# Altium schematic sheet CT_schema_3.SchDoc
size 334 x 183 mm
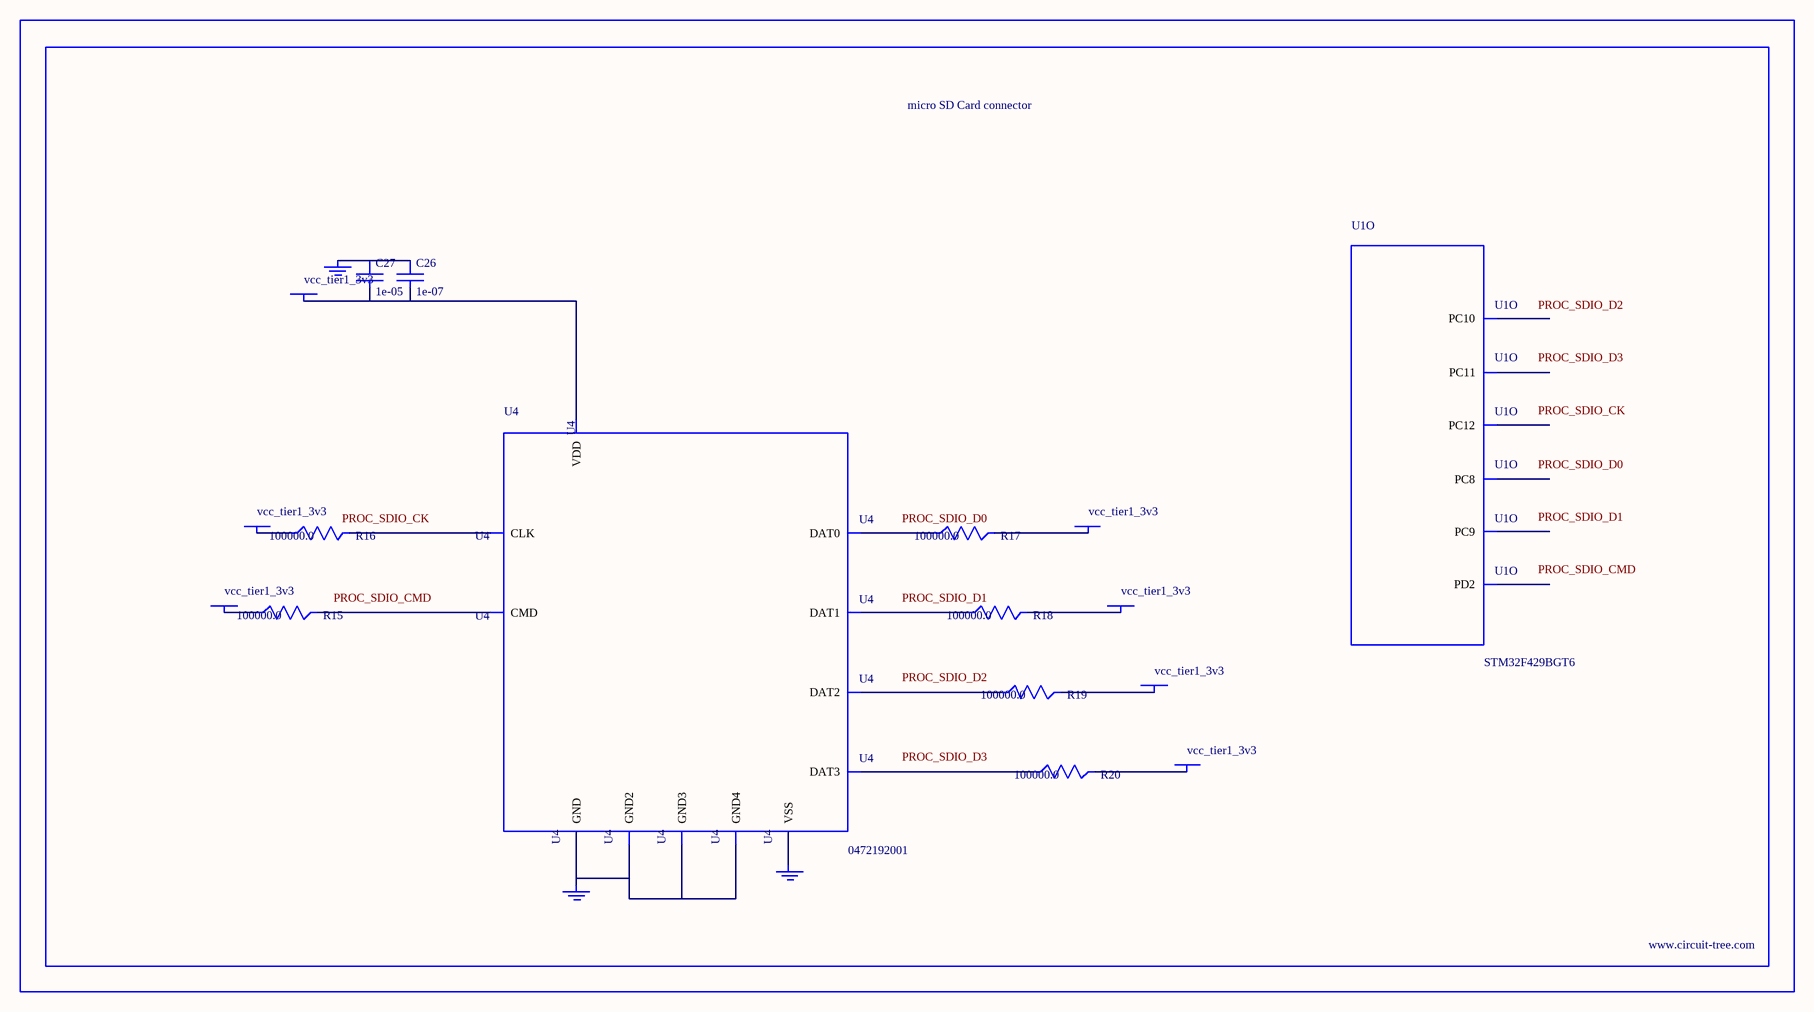
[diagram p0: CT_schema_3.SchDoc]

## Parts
BORDER2  (no value)
C26  1e-07  [C0402]
C27  1e-05  [C0805]
GND_INSTANCE_2_0  (no value)
GND_INSTANCE_2_1  (no value)
GND_INSTANCE_2_2  (no value)
POWER_INSTANCE_2_0  vcc_tier1_3v3
POWER_INSTANCE_2_1  vcc_tier1_3v3
POWER_INSTANCE_2_2  vcc_tier1_3v3
POWER_INSTANCE_2_3  vcc_tier1_3v3
POWER_INSTANCE_2_4  vcc_tier1_3v3
POWER_INSTANCE_2_5  vcc_tier1_3v3
POWER_INSTANCE_2_6  vcc_tier1_3v3
R15  100000.0  [R0603]
R16  100000.0  [R0603]
R17  100000.0  [R0603]
R18  100000.0  [R0603]
R19  100000.0  [R0603]
R20  100000.0  [R0603]
U1  STM32F429BGT6  [LQFP208]  (part O of 17)
U4  0472192001  [MOLEX_47219-2001]

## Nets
NetC26_1: C26.1 C27.1 GND_INSTANCE_2_0.0(GND)
NetC26_2: C26.2 C27.2 POWER_INSTANCE_2_3.0(PWR) U4.4(VDD)
NetGND_INSTANCE_2_1_0: GND_INSTANCE_2_1.0(GND) U4.6(VSS)
NetGND_INSTANCE_2_2_0: GND_INSTANCE_2_2.0(GND) U4.G1(GND) U4.G2(GND2) U4.G3(GND3) U4.G4(GND4)
NetPOWER_INSTANCE_2_0_0: POWER_INSTANCE_2_0.0(PWR) R19.2
NetPOWER_INSTANCE_2_1_0: POWER_INSTANCE_2_1.0(PWR) R20.2
NetPOWER_INSTANCE_2_2_0: POWER_INSTANCE_2_2.0(PWR) R15.1
NetPOWER_INSTANCE_2_4_0: POWER_INSTANCE_2_4.0(PWR) R16.1
NetPOWER_INSTANCE_2_5_0: POWER_INSTANCE_2_5.0(PWR) R17.2
NetPOWER_INSTANCE_2_6_0: POWER_INSTANCE_2_6.0(PWR) R18.2
NetR15_2: R15.2 U4.3(CMD)
NetR16_2: R16.2 U4.5(CLK)
NetR17_1: R17.1 U4.7(DAT0)
NetR18_1: R18.1 U4.8(DAT1)
NetR19_1: R19.1 U4.1(DAT2)
NetR20_1: R20.1 U4.2(DAT3)

Not connected (* = marked no-connect by the designer): U1 140(PC8) 141(PC9) 161(PC10) 162(PC11) 163(PC12) 166(PD2)

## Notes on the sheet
- Labels drawn without touching a wire or pin: PROC_SDIO_CK, PROC_SDIO_CMD, PROC_SDIO_D0, PROC_SDIO_D1, PROC_SDIO_D2, PROC_SDIO_D3

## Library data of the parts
BORDER2 = BORDER_PAGE2
C26 = C0402C104K3RACTU
C27 = C0805C106K8RACTU
GND_INSTANCE_2_0-GND_INSTANCE_2_2 = GND
POWER_INSTANCE_2_0-POWER_INSTANCE_2_6 = PWR
R15-R20 = RC0603JR-07100KL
